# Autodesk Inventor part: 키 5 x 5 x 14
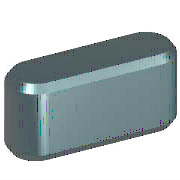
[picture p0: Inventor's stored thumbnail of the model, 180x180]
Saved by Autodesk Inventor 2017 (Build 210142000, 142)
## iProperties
IsCustomPart: 1
Created: 2012-02
Part Number: 키 5 x 5 x 14
Material: 강철, 연강
Description: 키 및 해당 키홈
Document SubType Name: Modeling
Standard: KS B 1311
Designer: mduedu
Standards Organization: KS
Language: ko-KR
Size Designation: 4 x 4 x 12
Categories: <MemberInstance><Categories><Category DisplayName="샤프트 부품" InternalName="7f7aeb1f-a693-4053-b835-cee3144e0d98" Mnemonic="SHFT"><Category DisplayName="키" Interna
Density: 1 g/cm^3
Appearance: 노란색
Author: mduedu
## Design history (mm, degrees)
workplane "Work Plane1"
workplane "Work Plane2"
sketch "스케치1"
  geometry: L1 (2.5, 2.5)-(11.5, 2.5); L2 (11.5, -2.5)-(2.5, -2.5); L3 (0, 8.9)-(0, -4.4) reference; L4 (-2.8, 0)-(16.8, 0) reference; L5 (14, 0)-(14, 7); A1 r 2.5 centre (2.5, 0) between (2.5, 2.5) and (2.5, -2.5); A2 r 2.5 centre (11.5, 0) between (11.5, -2.5) and (11.5, 2.5)
  constraints: 6 end point, 5 point on circle, 4 tangent, 3 point on line, 2 centre point, 1 horizontal, 1 parallel, 1 perpendicular
  dimensions: "d0" = 2.5 radius of A1 (= 0.5 x PB); "d13" = 2.5 radius of A2 (= 0.5 x PB); "d14" = 14 distance between parallel lines of L5 L3 (= NLG)
extrude "본체1" new body sketch "스케치1" taper "d3" = 0 deg; stored distance "d4" = 10
workplane "Work Plane3"
body "Solid1"
chamfer "모따기1" distance "d8" = 0.25 (= PHH); stored, may be unused: second distance "d9" = 0.25 (= PHH), angle "d15" = 45 deg
other parameters: "d1" = -3 (= -PNT), "d2" = 2 (= PH - PNT), "NLG" = 14 [user parameter; used in 3 equation terms], "PB" = 5 [user parameter; used in 2 equation terms], "PNT" = 3 [user parameter; used in 2 equation terms], "PH" = 5 [user parameter; used in 1 equation term], "PHH" = 0.25 [user parameter; used in 2 equation terms], "d10" = 0, "d16" = 0, "d17" = 0, "d18" = 0, "PLB2" = 14 (= NLG) [user parameter], "WDMAX" = 12 [user parameter], "PLB1" = 14 (= NLG) [user parameter], "RR" = 0.08 [user parameter], "PUEB" = 1.8 [user parameter]
